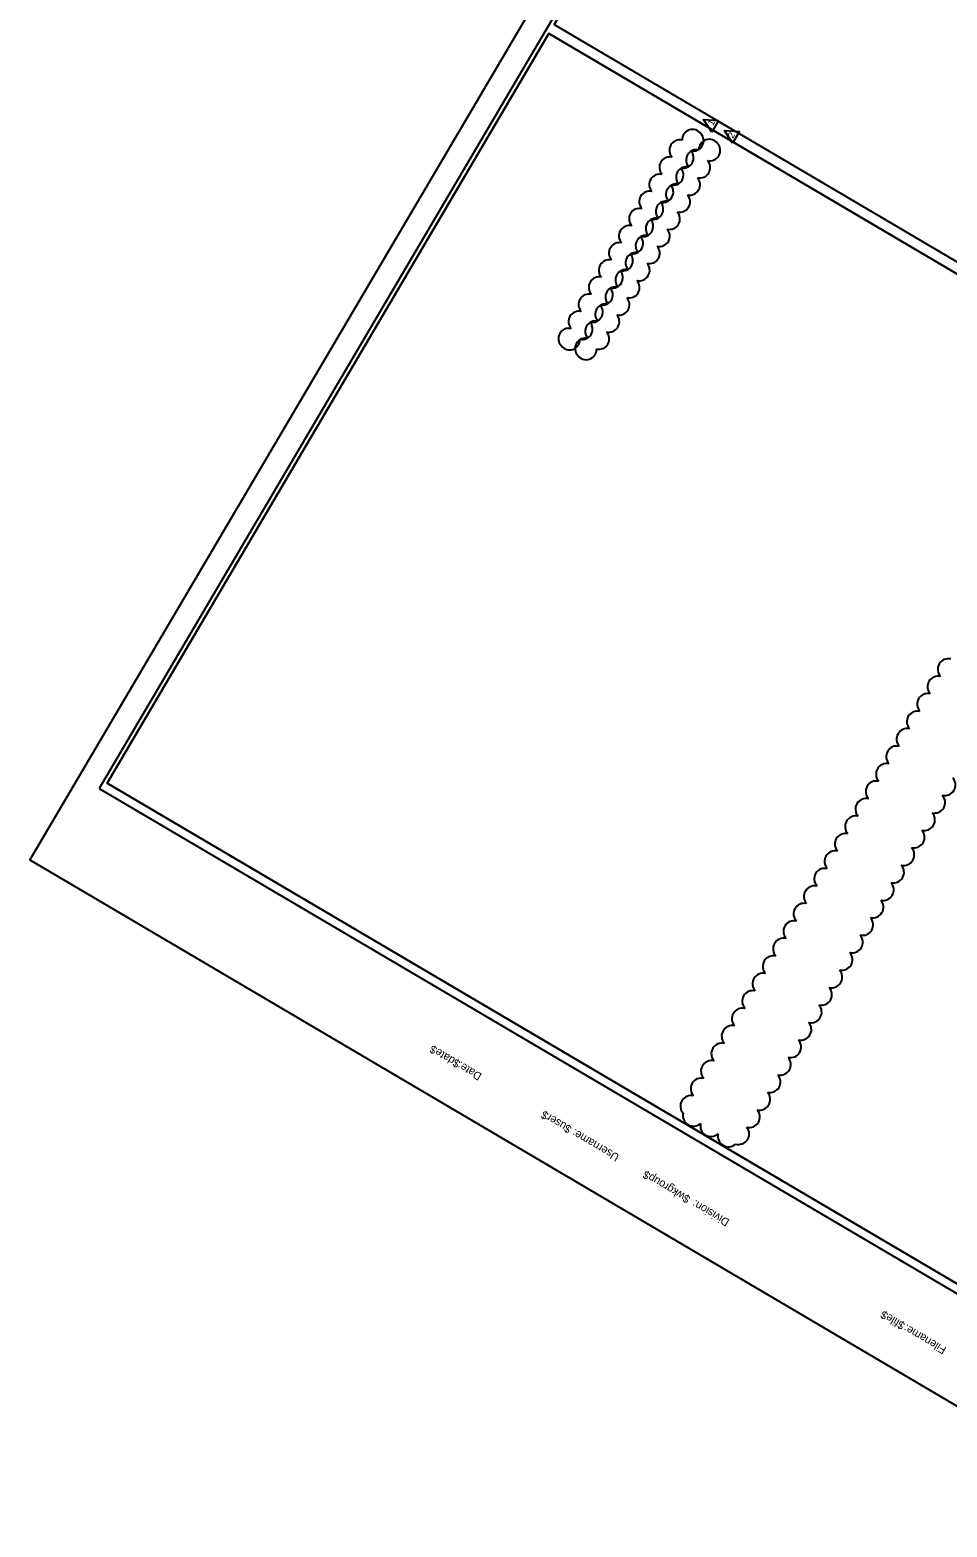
# Model space of a CAD drawing. Extents: x 12 to 1151523, y -64 to 610812.
# Drawn here: x 1151170.39 to 1151171.669, y 610615.226 to 610617.314 of the extents above; entities that cross this region are included whole.
import ezdxf

# ---------------------------------------------------------------- set-up
doc = ezdxf.new("R2010")
doc.units = 0
for name, color, linetype in [('ANNOTATION', 7, 'Continuous'), ('BORDER', 7, 'Continuous'), ('DIMENSIONS', 7, 'Continuous'), ('PLOT BOUNDARY', 7, 'Continuous')]:
    doc.layers.add(name, color=color, linetype=linetype)

msp = doc.modelspace()

# ---------------------------------------------------------------- linework, layer by layer
at = {"layer": 'ANNOTATION'}
for points in [[(1151171.9166, 610616.8528), (1151172.5327, 610617.8987), (1151171.737, 610618.3673), (1151171.121, 610617.3214)], [(1151171.9166, 610616.8528), (1151172.5327, 610617.8987), (1151171.737, 610618.3673), (1151171.121, 610617.3214)], [(1151170.4975, 610616.263), (1151171.1137, 610617.309), (1151172.6047, 610616.4307), (1151171.9886, 610615.3847)], [(1151171.9886, 610615.3847), (1151172.6047, 610616.4307), (1151171.1137, 610617.309), (1151170.4975, 610616.263)]]:
    msp.add_lwpolyline(points, close=True, dxfattribs=at)
for centre, radius, start, end in [((1151171.3141, 610617.1605), 0.0145, 36.3027, 181.3027), ((1151171.315, 610617.1594), 0.0145, 257.0011, 42.0011), ((1151171.2963, 610617.146), 0.0145, 77.0011, 222.0011), ((1151171.301, 610617.1355), 0.0145, 257.0011, 42.0011), ((1151171.3196, 610617.1323), 0.0145, 77.0011, 222.0011), ((1151171.3374, 610617.1468), 0.0145, 36.3027, 181.3027), ((1151171.3383, 610617.1457), 0.0145, 257.0011, 42.0011), ((1151171.2823, 610617.1221), 0.0145, 77.0011, 222.0011), ((1151171.2869, 610617.1116), 0.0145, 257.0011, 42.0011), ((1151171.3055, 610617.1084), 0.0145, 77.0011, 222.0011), ((1151171.3242, 610617.1218), 0.0145, 257.0011, 42.0011), ((1151171.2682, 610617.0982), 0.0145, 77.0011, 222.0011), ((1151171.3101, 610617.0979), 0.0145, 257.0011, 42.0011), ((1151171.2541, 610617.0743), 0.0145, 77.0011, 222.0011), ((1151171.2728, 610617.0877), 0.0145, 257.0011, 42.0011), ((1151171.2914, 610617.0845), 0.0145, 77.0011, 222.0011), ((1151171.2961, 610617.074), 0.0145, 257.0011, 42.0011), ((1151171.24, 610617.0504), 0.0145, 77.0011, 222.0011), ((1151171.2587, 610617.0638), 0.0145, 257.0011, 42.0011), ((1151171.2773, 610617.0606), 0.0145, 77.0011, 222.0011), ((1151171.282, 610617.0501), 0.0145, 257.0011, 42.0011), ((1151171.2259, 610617.0265), 0.0145, 77.0011, 222.0011), ((1151171.2447, 610617.0399), 0.0145, 257.0011, 42.0011), ((1151171.2633, 610617.0367), 0.0145, 77.0011, 222.0011), ((1151171.2119, 610617.0026), 0.0145, 77.0011, 222.0011), ((1151171.2306, 610617.016), 0.0145, 257.0011, 42.0011), ((1151171.2492, 610617.0128), 0.0145, 77.0011, 222.0011), ((1151171.2679, 610617.0262), 0.0145, 257.0011, 42.0011), ((1151171.2165, 610616.9921), 0.0145, 257.0011, 42.0011), ((1151171.2351, 610616.9889), 0.0145, 77.0011, 222.0011), ((1151171.2538, 610617.0023), 0.0145, 257.0011, 42.0011), ((1151171.1978, 610616.9787), 0.0145, 77.0011, 222.0011), ((1151171.2024, 610616.9682), 0.0145, 257.0011, 42.0011), ((1151171.221, 610616.965), 0.0145, 77.0011, 222.0011), ((1151171.2398, 610616.9784), 0.0145, 257.0011, 42.0011), ((1151171.1837, 610616.9548), 0.0145, 77.0011, 222.0011), ((1151171.1884, 610616.9443), 0.0145, 257.0011, 42.0011), ((1151171.207, 610616.9411), 0.0145, 77.0011, 222.0011), ((1151171.2257, 610616.9545), 0.0145, 257.0011, 42.0011), ((1151171.1696, 610616.9309), 0.0145, 77.0011, 222.0011), ((1151171.2116, 610616.9306), 0.0145, 257.0011, 42.0011), ((1151171.1556, 610616.907), 0.0145, 77.0011, 222.0011), ((1151171.1743, 610616.9204), 0.0145, 257.0011, 42.0011), ((1151171.1929, 610616.9172), 0.0145, 77.0011, 222.0011), ((1151171.1975, 610616.9067), 0.0145, 257.0011, 42.0011), ((1151171.1415, 610616.8831), 0.0145, 77.0011, 222.0011), ((1151171.1602, 610616.8965), 0.0145, 257.0011, 42.0011), ((1151171.1788, 610616.8933), 0.0145, 77.0011, 222.0011), ((1151171.1834, 610616.8828), 0.0145, 257.0011, 42.0011), ((1151171.1424, 610616.882), 0.0145, 216.3027, 1.3027), ((1151171.1647, 610616.8694), 0.0145, 77.0011, 222.0011), ((1151171.1656, 610616.8683), 0.0145, 216.3027, 1.3027), ((1151171.6708, 610616.422), 0.0148, 77.0011, 222.0011), ((1151171.6565, 610616.3976), 0.0148, 77.0011, 222.0011), ((1151171.6421, 610616.3733), 0.0148, 77.0011, 222.0011), ((1151171.6277, 610616.3489), 0.0148, 77.0011, 222.0011), ((1151171.6134, 610616.3245), 0.0148, 77.0011, 222.0011), ((1151171.599, 610616.3002), 0.0148, 77.0011, 222.0011), ((1151171.5847, 610616.2758), 0.0148, 77.0011, 222.0011), ((1151171.5703, 610616.2514), 0.0148, 77.0011, 222.0011), ((1151171.666, 610616.2607), 0.0148, 257.0011, 42.0011), ((1151171.6516, 610616.2363), 0.0148, 257.0011, 42.0011), ((1151171.556, 610616.227), 0.0148, 77.0011, 222.0011), ((1151171.5416, 610616.2027), 0.0148, 77.0011, 222.0011), ((1151171.6373, 610616.2119), 0.0148, 257.0011, 42.0011), ((1151171.5273, 610616.1783), 0.0148, 77.0011, 222.0011), ((1151171.6229, 610616.1876), 0.0148, 257.0011, 42.0011), ((1151171.5129, 610616.1539), 0.0148, 77.0011, 222.0011), ((1151171.6086, 610616.1632), 0.0148, 257.0011, 42.0011), ((1151171.4985, 610616.1296), 0.0148, 77.0011, 222.0011), ((1151171.5942, 610616.1388), 0.0148, 257.0011, 42.0011), ((1151171.4842, 610616.1052), 0.0148, 77.0011, 222.0011), ((1151171.5799, 610616.1144), 0.0148, 257.0011, 42.0011), ((1151171.5655, 610616.0901), 0.0148, 257.0011, 42.0011), ((1151171.4698, 610616.0808), 0.0148, 77.0011, 222.0011), ((1151171.4555, 610616.0564), 0.0148, 77.0011, 222.0011), ((1151171.5512, 610616.0657), 0.0148, 257.0011, 42.0011), ((1151171.4411, 610616.0321), 0.0148, 77.0011, 222.0011), ((1151171.5368, 610616.0413), 0.0148, 257.0011, 42.0011), ((1151171.4268, 610616.0077), 0.0148, 77.0011, 222.0011), ((1151171.5224, 610616.017), 0.0148, 257.0011, 42.0011), ((1151171.4124, 610615.9833), 0.0148, 77.0011, 222.0011), ((1151171.5081, 610615.9926), 0.0148, 257.0011, 42.0011), ((1151171.3981, 610615.959), 0.0148, 77.0011, 222.0011), ((1151171.4937, 610615.9682), 0.0148, 257.0011, 42.0011), ((1151171.4794, 610615.9438), 0.0148, 257.0011, 42.0011), ((1151171.3837, 610615.9346), 0.0148, 77.0011, 222.0011), ((1151171.3694, 610615.9102), 0.0148, 77.0011, 222.0011), ((1151171.465, 610615.9195), 0.0148, 257.0011, 42.0011), ((1151171.355, 610615.8858), 0.0148, 77.0011, 222.0011), ((1151171.4507, 610615.8951), 0.0148, 257.0011, 42.0011), ((1151171.3406, 610615.8615), 0.0148, 77.0011, 222.0011), ((1151171.4363, 610615.8707), 0.0148, 257.0011, 42.0011), ((1151171.3263, 610615.8371), 0.0148, 77.0011, 222.0011), ((1151171.422, 610615.8464), 0.0148, 257.0011, 42.0011), ((1151171.3119, 610615.8127), 0.0148, 77.0011, 222.0011), ((1151171.4076, 610615.822), 0.0148, 257.0011, 42.0011), ((1151171.3932, 610615.7976), 0.0148, 257.0011, 42.0011), ((1151171.3154, 610615.7995), 0.0148, 167.0011, 312.0011), ((1151171.3397, 610615.7851), 0.0148, 167.0011, 312.0011), ((1151171.3641, 610615.7708), 0.0148, 167.0011, 312.0011), ((1151171.3783, 610615.774), 0.0148, 253.3175, 38.3175)]:
    msp.add_arc(centre, radius, start, end, dxfattribs=at)
at = {"layer": 'BORDER'}
for p, q in [((1151171.8397, 610618.5535), (1151170.4863, 610616.2558)), ((1151170.4863, 610616.2558), (1151171.9941, 610615.3677))]:
    msp.add_line(p, q, dxfattribs=at)
at = {"layer": 'DIMENSIONS'}
for p, q in [((1151171.3504, 610617.1876), (1151171.3408, 610617.1713)), ((1151171.3796, 610617.1719), (1151171.37, 610617.1557))]:
    msp.add_line(p, q, dxfattribs=at)
for points in [[(1151171.3408, 610617.1713), (1151171.3293, 610617.189), (1151171.3504, 610617.1876)], [(1151171.37, 610617.1557), (1151171.3586, 610617.1734), (1151171.3796, 610617.1719)]]:
    msp.add_lwpolyline(points, dxfattribs=at)
at = {"layer": 'PLOT BOUNDARY'}
msp.add_lwpolyline([(1151171.9696, 610615.2256), (1151173.4076, 610617.6669), (1151171.8279, 610618.5973), (1151170.3899, 610616.156)], close=True, dxfattribs=at)

# ---------------------------------------------------------------- texts
at = {"layer": 'BORDER'}
for s, p in [('$date$', (1151170.9911, 610615.875)), ('Date:', (1151171.0211, 610615.8574)), ('$user$', (1151171.1464, 610615.7836)), ('Username:', (1151171.2128, 610615.7444)), ('$wkgroup$', (1151171.3119, 610615.6861)), ('Division:', (1151171.3665, 610615.6539)), ('$file$', (1151171.6112, 610615.5098)), ('Filename:', (1151171.669, 610615.4757))]:
    msp.add_text(s, height=0.01116, rotation=149.5011, dxfattribs=at).set_placement(p)
at = {"layer": 'DIMENSIONS'}
for s, p in [('1', (1151171.3423, 610617.1795)), ('2', (1151171.3704, 610617.1619))]:
    msp.add_text(s, height=0.00907, rotation=59.5011, dxfattribs=at).set_placement(p)

doc.saveas('drawing.dxf')
